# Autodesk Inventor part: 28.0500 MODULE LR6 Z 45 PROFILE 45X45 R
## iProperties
Created: 2007-06
Part Number: 28.0500 MODULE LR6 Z 45 PROFILE 45X45 R
Material: Aluminum-6061
Document SubType Name: Modeling
Designer: Andy Moles
Density: 2.71 g/cm^3
Author: Andy Moles
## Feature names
1. Extrusion1
2. Extrusion2
3. Mirror1
